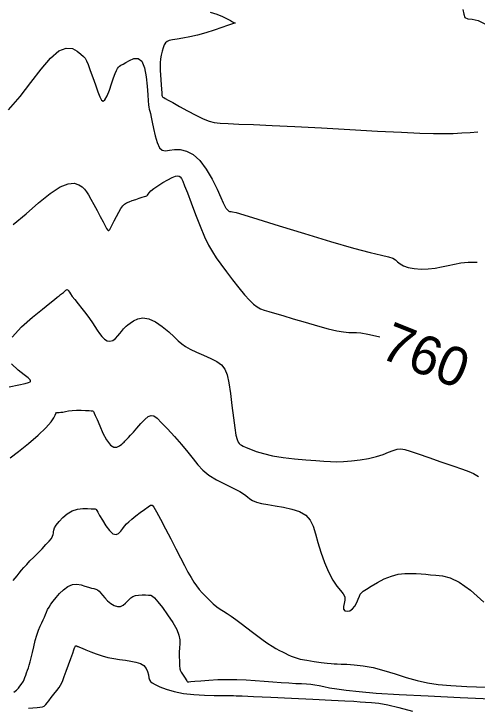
# Model space of a CAD drawing. Extents: x 2566142 to 2571431, y 418755 to 421584.
# Drawn here: x 2570563.2 to 2570801.1, y 420602.2 to 420960.2 of the extents above; entities that cross this region are included whole.
import ezdxf

# ---------------------------------------------------------------- set-up
doc = ezdxf.new("R2010")
doc.units = 0
for name, color, linetype in [('Contour_ADS_Label_Major', 7, 'Continuous'), ('Contour_ADS_Major', 7, 'Continuous'), ('Contour_ADS_Minor', 7, 'Continuous')]:
    doc.layers.add(name, color=color, linetype=linetype)

msp = doc.modelspace()

# ---------------------------------------------------------------- linework, layer by layer
at = {"layer": 'Contour_ADS_Major'}
for points in [[(2570562.7, 420851.9), (2570569.36, 420857.45), (2570575.83, 420862.95), (2570581.81, 420867.74), (2570586.95, 420871.2), (2570591.03, 420872.87), (2570594.14, 420873.09), (2570596.46, 420872.36), (2570598.16, 420871.2), (2570599.42, 420870.01), (2570600.45, 420868.71), (2570601.46, 420867.09), (2570602.64, 420864.95), (2570604.14, 420862.17), (2570605.83, 420859.04), (2570607.5, 420855.93), (2570608.93, 420853.22), (2570609.99, 420851.21), (2570610.71, 420849.88), (2570611.22, 420849.11), (2570611.59, 420848.8), (2570611.94, 420848.87), (2570612.35, 420849.36), (2570612.88, 420850.31), (2570613.62, 420851.79), (2570614.61, 420853.78), (2570615.76, 420856.06), (2570616.96, 420858.29), (2570618.07, 420860.19), (2570619.03, 420861.53), (2570619.95, 420862.41), (2570620.98, 420863.02), (2570622.27, 420863.56), (2570623.93, 420864.17), (2570625.77, 420864.81), (2570627.57, 420865.42), (2570629.11, 420865.91), (2570630.21, 420866.24), (2570630.94, 420866.47), (2570631.41, 420866.69), (2570631.75, 420867.01), (2570632.09, 420867.49), (2570632.61, 420868.19), (2570633.52, 420869.14), (2570634.99, 420870.35), (2570637.13, 420871.83), (2570639.68, 420873.41), (2570642.26, 420874.88), (2570644.51, 420876.04), (2570646.16, 420876.73), (2570647.29, 420876.97), (2570648.05, 420876.82), (2570648.63, 420876.35), (2570649.19, 420875.56), (2570649.88, 420874.17), (2570650.85, 420871.82), (2570652.25, 420868.18), (2570654.17, 420863.06), (2570656.44, 420857.06), (2570658.84, 420850.94), (2570661.13, 420845.47), (2570663.16, 420841.2), (2570665.08, 420837.8), (2570667.12, 420834.72), (2570669.5, 420831.44), (2570672.36, 420827.56), (2570675.52, 420823.35), (2570678.7, 420819.23), (2570681.63, 420815.64), (2570684.11, 420812.89), (2570686.2, 420810.9), (2570688.07, 420809.51), (2570689.86, 420808.53), (2570691.74, 420807.77), (2570694.04, 420807.07), (2570697.09, 420806.22), (2570701.24, 420805.05), (2570706.65, 420803.44), (2570712.81, 420801.59), (2570719.04, 420799.76), (2570724.65, 420798.24), (2570729.11, 420797.21), (2570732.52, 420796.63), (2570735.13, 420796.37), (2570737.21, 420796.3), (2570739.08, 420796.29), (2570741.42, 420796.1), (2570744.97, 420795.51), (2570750.48, 420794.27), (2570751.11, 420794.11)], [(2570570.7, 420603.19), (2570575.15, 420603.52), (2570577.76, 420603.88), (2570578.61, 420604.2), (2570579.07, 420604.55), (2570579.54, 420605.04), (2570580.14, 420605.8), (2570581.03, 420606.95), (2570582.27, 420608.55), (2570583.71, 420610.4), (2570585.14, 420612.25), (2570586.33, 420613.84), (2570587.16, 420615.03), (2570587.74, 420616.09), (2570588.28, 420617.4), (2570589, 420619.35), (2570590.01, 420622.16), (2570591.21, 420625.46), (2570592.4, 420628.72), (2570593.37, 420631.43), (2570594.01, 420633.19), (2570594.34, 420634.14), (2570594.5, 420634.57), (2570594.56, 420634.74), (2570594.64, 420634.88), (2570594.73, 420635.02), (2570594.84, 420635.14), (2570594.97, 420635.21), (2570595.11, 420635.21), (2570595.27, 420635.16), (2570595.43, 420635.09), (2570595.59, 420635.01), (2570595.78, 420634.93), (2570596.15, 420634.79), (2570596.89, 420634.5), (2570598.16, 420633.96), (2570600.1, 420633.13), (2570602.58, 420632.12), (2570605.42, 420631.05), (2570608.44, 420630.07), (2570611.47, 420629.28), (2570614.49, 420628.67), (2570617.46, 420628.18), (2570620.39, 420627.76), (2570623.21, 420627.35), (2570625.83, 420626.83), (2570628.1, 420626.11), (2570629.88, 420625.05), (2570631.08, 420623.6), (2570631.81, 420621.92), (2570632.23, 420620.24), (2570632.49, 420618.79), (2570632.76, 420617.71), (2570633.25, 420616.9), (2570634.18, 420616.15), (2570635.77, 420615.29), (2570638.19, 420614.18), (2570641.44, 420612.94), (2570645.47, 420611.74), (2570650.21, 420610.77), (2570655.55, 420610.14), (2570661, 420609.82), (2570666, 420609.69), (2570669.99, 420609.68), (2570672.58, 420609.68), (2570673.99, 420609.69), (2570674.62, 420609.7), (2570674.85, 420609.7), (2570675.02, 420609.7), (2570675.19, 420609.69), (2570675.38, 420609.68), (2570675.6, 420609.66), (2570676.01, 420609.63), (2570677.32, 420609.57), (2570680.43, 420609.43), (2570686.19, 420609.17), (2570695.07, 420608.78), (2570705.82, 420608.31), (2570716.78, 420607.8), (2570726.3, 420607.34), (2570733.12, 420606.96), (2570737.72, 420606.66), (2570740.97, 420606.42), (2570743.75, 420606.22), (2570746.83, 420606.01), (2570750.56, 420605.63), (2570755.19, 420604.87), (2570760.95, 420603.55), (2570767.91, 420601.57)]]:
    msp.add_lwpolyline(points, dxfattribs=at)
at = {"layer": 'Contour_ADS_Minor'}
for points in [[(2570663.9, 420961.1), (2570667.37, 420960.04), (2570670.29, 420958.86), (2570672.63, 420957.72), (2570674.36, 420956.79), (2570675.51, 420956.18), (2570676.19, 420955.84), (2570676.53, 420955.68), (2570676.69, 420955.61), (2570676.78, 420955.57), (2570676.83, 420955.53), (2570676.84, 420955.5), (2570676.81, 420955.47), (2570676.75, 420955.44), (2570676.67, 420955.41), (2570676.57, 420955.39), (2570676.47, 420955.37), (2570676.33, 420955.34), (2570675.9, 420955.21), (2570674.86, 420954.87), (2570672.92, 420954.2), (2570669.89, 420953.13), (2570666.03, 420951.83), (2570661.75, 420950.47), (2570657.45, 420949.26), (2570653.45, 420948.35), (2570649.92, 420947.69), (2570646.93, 420947.21), (2570644.58, 420946.83), (2570642.91, 420946.45), (2570641.79, 420945.96), (2570641.02, 420945.25), (2570640.41, 420944.21), (2570639.82, 420942.74), (2570639.27, 420940.96), (2570638.79, 420939.01), (2570638.45, 420937.01), (2570638.29, 420935.07), (2570638.26, 420933.13), (2570638.34, 420931.08), (2570638.47, 420928.83), (2570638.62, 420926.33), (2570638.77, 420923.79), (2570638.92, 420921.47), (2570639.05, 420919.64), (2570639.17, 420918.47), (2570639.3, 420917.84), (2570639.47, 420917.55), (2570639.71, 420917.39), (2570640.1, 420917.16), (2570640.87, 420916.71), (2570642.31, 420915.88), (2570644.7, 420914.54), (2570648.19, 420912.62), (2570652.35, 420910.37), (2570656.63, 420908.15), (2570660.44, 420906.29), (2570663.44, 420905.05), (2570666.1, 420904.34), (2570669.1, 420903.97), (2570673.13, 420903.75), (2570678.77, 420903.53), (2570686.26, 420903.23), (2570695.76, 420902.82), (2570707.42, 420902.25)], [(2570793.83, 420962.37), (2570794.25, 420960.06), (2570794.82, 420958.41), (2570796.3, 420957.73), (2570798.65, 420957.46), (2570801.63, 420956.84), (2570804.99, 420955.09), (2570808.5, 420951.68), (2570811.96, 420947.09), (2570815.19, 420942.08), (2570818.01, 420937.38), (2570820.33, 420933.56), (2570822.49, 420930.46), (2570824.92, 420927.76), (2570828.03, 420925.15), (2570832.08, 420922.38), (2570836.61, 420919.63), (2570841, 420917.15), (2570844.61, 420915.2), (2570846.97, 420913.96), (2570848.29, 420913.29), (2570848.91, 420913), (2570849.2, 420912.87)], [(2570560.43, 420910.9), (2570566.27, 420917.78), (2570571.86, 420924.96), (2570577.11, 420931.74), (2570581.94, 420937.4), (2570586.27, 420941.19), (2570590.02, 420942.65), (2570593.16, 420942.31), (2570595.67, 420940.97), (2570597.55, 420939.44), (2570598.82, 420938.31), (2570599.69, 420937.34), (2570600.4, 420936.08), (2570601.22, 420934.1)], [(2570601.22, 420934.1), (2570602.32, 420931.11), (2570603.63, 420927.45), (2570604.98, 420923.63), (2570606.22, 420920.17), (2570607.25, 420917.49), (2570608.13, 420915.82), (2570608.98, 420915.28), (2570609.91, 420916.04), (2570611, 420918.11), (2570612.18, 420921.05), (2570613.34, 420924.29), (2570614.35, 420927.27), (2570615.15, 420929.53), (2570615.77, 420931.12), (2570616.3, 420932.18), (2570616.81, 420932.87), (2570617.39, 420933.35), (2570618.15, 420933.77), (2570619.2, 420934.31), (2570620.67, 420935.14), (2570622.6, 420936.28), (2570624.78, 420937.22), (2570626.94, 420937.3), (2570628.79, 420935.86), (2570630.15, 420932.51), (2570631.04, 420927.9), (2570631.6, 420922.94), (2570631.93, 420918.56), (2570632.14, 420915.45), (2570632.3, 420913.43), (2570632.44, 420912.14), (2570632.63, 420911.18), (2570632.89, 420910.19), (2570633.25, 420908.92), (2570633.7, 420907.13), (2570634.25, 420904.59), (2570634.91, 420901.21), (2570635.71, 420897.47), (2570636.69, 420893.99), (2570637.87, 420891.39), (2570639.3, 420890.11), (2570641.04, 420889.85), (2570643.13, 420890.14), (2570645.63, 420890.48), (2570648.56, 420890.43), (2570651.81, 420889.67), (2570655.23, 420887.91), (2570658.66, 420884.87), (2570661.96, 420880.42), (2570664.97, 420875.23), (2570667.53, 420870.09), (2570669.48, 420865.84), (2570670.71, 420863.09), (2570671.38, 420861.61), (2570671.68, 420860.96), (2570671.83, 420860.7), (2570671.99, 420860.45), (2570672.19, 420860.18), (2570672.44, 420859.87), (2570672.72, 420859.55), (2570673.02, 420859.24), (2570673.34, 420858.96), (2570673.63, 420858.73), (2570673.88, 420858.58), (2570674.07, 420858.53), (2570674.26, 420858.55), (2570674.49, 420858.58), (2570674.83, 420858.59), (2570675.5, 420858.48), (2570677.33, 420857.99), (2570681.33, 420856.81), (2570688.5, 420854.6), (2570699.36, 420851.24), (2570712.45, 420847.2), (2570725.84, 420843.16), (2570737.59, 420839.76), (2570746.2, 420837.5), (2570751.95, 420836.15), (2570755.56, 420835.31), (2570757.74, 420834.6), (2570759.17, 420833.71), (2570760.29, 420832.66), (2570761.5, 420831.59), (2570763.22, 420830.6), (2570765.72, 420829.81), (2570768.85, 420829.26), (2570772.36, 420828.99), (2570775.97, 420829.04), (2570779.48, 420829.41), (2570782.87, 420830.03), (2570786.19, 420830.78), (2570789.46, 420831.55), (2570792.8, 420832.22), (2570796.56, 420832.59), (2570801.16, 420832.44)], [(2570707.42, 420902.25), (2570721.11, 420901.53), (2570735.73, 420900.72), (2570749.9, 420899.94), (2570762.22, 420899.29), (2570771.7, 420898.85), (2570778.76, 420898.63), (2570784.19, 420898.6), (2570788.79, 420898.72), (2570793.2, 420898.96), (2570797.46, 420899.25), (2570801.43, 420899.5)], [(2570562.17, 420793.96), (2570567, 420799.29), (2570572.64, 420804.27), (2570577.83, 420808.42), (2570581.56, 420811.39), (2570583.97, 420813.32), (2570585.43, 420814.52), (2570586.35, 420815.26), (2570587.05, 420815.81), (2570587.63, 420816.25), (2570588.13, 420816.63), (2570588.6, 420816.98), (2570589.05, 420817.36), (2570589.48, 420817.72), (2570589.87, 420818.04), (2570590.21, 420818.27), (2570590.48, 420818.37), (2570590.72, 420818.32), (2570590.97, 420818.1), (2570591.26, 420817.7), (2570591.66, 420817.09), (2570592.24, 420816.19), (2570593.11, 420814.93), (2570594.37, 420813.24), (2570596.07, 420811.09), (2570598.04, 420808.62), (2570600.07, 420806.05), (2570601.93, 420803.58), (2570603.49, 420801.36), (2570604.79, 420799.38), (2570605.96, 420797.57), (2570607.12, 420795.89), (2570608.36, 420794.31), (2570609.7, 420792.97), (2570611.08, 420792.08), (2570612.5, 420791.81), (2570613.91, 420792.28), (2570615.25, 420793.28), (2570616.48, 420794.55), (2570617.52, 420795.8), (2570618.33, 420796.8), (2570618.95, 420797.57), (2570619.45, 420798.17), (2570619.89, 420798.67), (2570620.33, 420799.14), (2570620.89, 420799.66), (2570621.71, 420800.31), (2570622.91, 420801.19), (2570624.59, 420802.29), (2570626.77, 420803.3), (2570629.39, 420803.8), (2570632.45, 420803.4), (2570635.85, 420801.85), (2570639.35, 420799.47), (2570642.65, 420796.75), (2570645.46, 420794.17), (2570647.6, 420792.11), (2570649.39, 420790.47), (2570651.26, 420789.08), (2570653.66, 420787.72), (2570656.86, 420786.25), (2570660.55, 420784.68), (2570664.23, 420783.04), (2570667.45, 420781.37), (2570669.82, 420779.65), (2570671.48, 420777.55), (2570672.64, 420774.65), (2570673.54, 420770.53), (2570674.36, 420765.01), (2570675.15, 420758.73), (2570675.89, 420752.53), (2570676.57, 420747.27), (2570677.2, 420743.59), (2570677.79, 420741.3), (2570678.33, 420740.01), (2570678.83, 420739.3), (2570679.33, 420738.82), (2570679.98, 420738.41), (2570680.97, 420737.93), (2570682.47, 420737.27), (2570684.66, 420736.33), (2570687.6, 420735.22)], [(2570560.77, 420768.42), (2570565.72, 420769.35), (2570568.95, 420770.05), (2570570.68, 420770.55), (2570571.42, 420770.91), (2570571.64, 420771.2), (2570571.7, 420771.51), (2570571.41, 420772.03), (2570570.42, 420772.99), (2570568.4, 420774.58), (2570565.26, 420776.99), (2570561.93, 420780.19)], [(2570561.25, 420731.81), (2570565.54, 420735.18), (2570570.57, 420739.28), (2570575.52, 420743.54), (2570579.61, 420747.38), (2570582.23, 420750.35), (2570583.65, 420752.47), (2570584.29, 420753.88), (2570584.63, 420754.73), (2570585.04, 420755.14), (2570585.6, 420755.27), (2570586.32, 420755.27), (2570587.21, 420755.29), (2570588.27, 420755.44), (2570589.56, 420755.7), (2570591.13, 420755.97), (2570593.04, 420756.2), (2570595.3, 420756.32), (2570597.68, 420756.35), (2570599.91, 420756.3), (2570601.72, 420756.22), (2570602.91, 420756.11), (2570603.57, 420755.98), (2570603.89, 420755.83), (2570604.04, 420755.66), (2570604.18, 420755.42), (2570604.45, 420754.85), (2570604.96, 420753.65), (2570605.86, 420751.52), (2570607.2, 420748.32), (2570608.89, 420744.6), (2570610.77, 420741.07), (2570612.68, 420738.47), (2570614.48, 420737.31), (2570616.09, 420737.31), (2570617.47, 420737.98), (2570618.54, 420738.84), (2570619.28, 420739.52), (2570619.79, 420740.01), (2570620.2, 420740.43), (2570620.63, 420740.89), (2570621.21, 420741.48), (2570622.01, 420742.32), (2570623.09, 420743.5), (2570624.52, 420745.12), (2570626.31, 420747.21), (2570628.31, 420749.47), (2570630.32, 420751.54), (2570632.14, 420753.07), (2570633.65, 420753.73), (2570635.09, 420753.45), (2570636.77, 420752.2), (2570639.03, 420749.95), (2570642.06, 420746.73), (2570645.59, 420742.88), (2570649.21, 420738.78), (2570652.51, 420734.82), (2570655.24, 420731.32), (2570657.67, 420728.25), (2570660.24, 420725.5), (2570663.36, 420722.97), (2570667.29, 420720.58), (2570671.63, 420718.34), (2570675.81, 420716.31), (2570679.26, 420714.53)], [(2570687.6, 420735.22), (2570691.37, 420734.06), (2570696.01, 420732.99), (2570701.48, 420732.12), (2570707.36, 420731.44), (2570713.13, 420730.9), (2570718.27, 420730.48), (2570722.41, 420730.14), (2570725.86, 420729.92), (2570729.08, 420729.84), (2570732.54, 420729.95), (2570736.58, 420730.27), (2570740.97, 420730.81), (2570745.36, 420731.55), (2570749.4, 420732.5), (2570752.82, 420733.61), (2570755.65, 420734.73), (2570758.02, 420735.7), (2570760.03, 420736.34), (2570761.88, 420736.5), (2570763.98, 420736.15), (2570766.79, 420735.28), (2570770.81, 420733.88), (2570776.27, 420732.01), (2570782.5, 420729.9), (2570788.57, 420727.84), (2570793.57, 420726.14), (2570796.92, 420724.94), (2570799.33, 420723.82), (2570801.85, 420722.22)], [(2570679.26, 420714.53), (2570681.59, 420713.04), (2570683.11, 420711.8), (2570684.33, 420710.77), (2570685.73, 420709.9), (2570687.72, 420709.15), (2570690.35, 420708.48), (2570693.58, 420707.83), (2570697.35, 420707.18), (2570701.56, 420706.45), (2570705.87, 420705.51), (2570709.86, 420704.2), (2570713.12, 420702.35), (2570715.36, 420699.84), (2570716.86, 420696.66), (2570718.02, 420692.82), (2570719.22, 420688.34), (2570720.77, 420683.3), (2570722.66, 420678.1), (2570724.75, 420673.2), (2570726.91, 420669.04), (2570729.03, 420665.95), (2570730.91, 420663.72), (2570732.35, 420661.99), (2570733.15, 420660.4), (2570733.22, 420658.69), (2570732.85, 420656.95), (2570732.46, 420655.35), (2570732.44, 420654.07), (2570733.1, 420653.26), (2570734.27, 420652.99), (2570735.69, 420653.28), (2570737.11, 420654.16), (2570738.31, 420655.62), (2570739.28, 420657.41), (2570740.03, 420659.21), (2570740.6, 420660.73), (2570741.07, 420661.76), (2570741.65, 420662.49), (2570742.63, 420663.24), (2570744.27, 420664.3), (2570746.75, 420665.87), (2570749.89, 420667.74), (2570753.41, 420669.58), (2570757.05, 420671.08), (2570760.57, 420671.99), (2570763.89, 420672.4), (2570766.97, 420672.47), (2570769.77, 420672.35), (2570772.3, 420672.18), (2570774.7, 420672), (2570777.2, 420671.78), (2570779.98, 420671.54), (2570783.24, 420671.16), (2570787.18, 420670.15), (2570791.96, 420667.9), (2570797.78, 420663.81), (2570804.64, 420657.58)], [(2570562.77, 420668.76), (2570563.82, 420669.93), (2570564.84, 420671.23), (2570565.9, 420672.6), (2570567.04, 420674.04), (2570568.32, 420675.53), (2570569.76, 420677.1), (2570571.4, 420678.83), (2570573.29, 420680.76), (2570575.41, 420682.9), (2570577.59, 420685.13), (2570579.61, 420687.24), (2570581.26, 420689.07), (2570582.37, 420690.48), (2570583.02, 420691.54), (2570583.33, 420692.37), (2570583.45, 420693.09), (2570583.51, 420693.84), (2570583.66, 420694.71), (2570584.07, 420695.82), (2570584.92, 420697.3), (2570586.32, 420699.17), (2570588.21, 420701.23), (2570590.5, 420703.15), (2570593.07, 420704.65), (2570595.82, 420705.51), (2570598.52, 420705.84), (2570600.95, 420705.84), (2570602.88, 420705.72), (2570604.14, 420705.63), (2570604.84, 420705.57), (2570605.18, 420705.52), (2570605.32, 420705.44), (2570605.45, 420705.27), (2570605.7, 420704.82), (2570606.22, 420703.87), (2570607.15, 420702.21), (2570608.57, 420699.75), (2570610.32, 420696.96), (2570612.21, 420694.43), (2570614.02, 420692.76), (2570615.59, 420692.37), (2570616.92, 420693.01), (2570618.07, 420694.23), (2570619.06, 420695.61), (2570619.98, 420696.81), (2570620.95, 420697.89), (2570622.15, 420699.02), (2570623.74, 420700.34), (2570625.79, 420701.97), (2570628.08, 420703.73), (2570630.29, 420705.39), (2570632.1, 420706.74), (2570633.3, 420707.54), (2570634.18, 420707.55), (2570635.09, 420706.49), (2570636.43, 420704.11), (2570638.46, 420700.29), (2570640.99, 420695.45), (2570643.74, 420690.17), (2570646.4, 420685), (2570648.75, 420680.41), (2570650.78, 420676.46), (2570652.55, 420673.1), (2570654.12, 420670.29), (2570655.56, 420667.97), (2570656.94, 420666), (2570658.37, 420664.2), (2570659.93, 420662.43), (2570661.68, 420660.55), (2570663.55, 420658.66), (2570665.46, 420656.87), (2570667.32, 420655.31), (2570669.06, 420654.05), (2570670.79, 420652.95), (2570672.64, 420651.81), (2570674.75, 420650.44), (2570677.22, 420648.69), (2570679.96, 420646.64), (2570682.83, 420644.44), (2570685.72, 420642.22)], [(2570563.08, 420611.43), (2570564.46, 420612.45), (2570565.49, 420613.46), (2570566.25, 420614.41), (2570566.83, 420615.23), (2570567.29, 420615.9), (2570567.67, 420616.48), (2570568.03, 420617.11), (2570568.39, 420617.89), (2570568.79, 420618.9), (2570569.22, 420620.09), (2570569.67, 420621.38), (2570570.12, 420622.68), (2570570.56, 420623.95), (2570571.01, 420625.32), (2570571.49, 420626.98), (2570572.02, 420629.09), (2570572.62, 420631.76), (2570573.3, 420634.77), (2570574.04, 420637.86), (2570574.86, 420640.74), (2570575.74, 420643.19), (2570576.62, 420645.24), (2570577.46, 420646.98), (2570578.2, 420648.51), (2570578.81, 420649.91), (2570579.33, 420651.23), (2570579.85, 420652.52), (2570580.45, 420653.82), (2570581.18, 420655.17), (2570582.12, 420656.62), (2570583.31, 420658.23), (2570584.79, 420660.05), (2570586.6, 420662.06), (2570588.66, 420664.04), (2570590.88, 420665.69), (2570593.17, 420666.73), (2570595.45, 420666.97), (2570597.63, 420666.61), (2570599.65, 420665.95), (2570601.43, 420665.3), (2570602.93, 420664.89), (2570604.17, 420664.64), (2570605.21, 420664.39), (2570606.11, 420663.99), (2570606.91, 420663.31), (2570607.73, 420662.37), (2570608.66, 420661.2), (2570609.82, 420659.85), (2570611.26, 420658.39), (2570612.91, 420657), (2570614.64, 420655.92), (2570616.32, 420655.35), (2570617.87, 420655.47), (2570619.25, 420656.11), (2570620.46, 420657.06), (2570621.5, 420658.11), (2570622.39, 420659.08), (2570623.25, 420659.89), (2570624.25, 420660.55), (2570625.52, 420661.01), (2570627.16, 420661.27), (2570628.99, 420661.36), (2570630.78, 420661.36), (2570632.3, 420661.31), (2570633.41, 420661.21), (2570634.34, 420660.82), (2570635.45, 420659.81), (2570637.07, 420657.89), (2570639.4, 420654.88), (2570642.11, 420651.15), (2570644.73, 420647.22), (2570646.79, 420643.6), (2570647.95, 420640.67), (2570648.38, 420638.29), (2570648.36, 420636.2), (2570648.18, 420634.13), (2570648.08, 420631.89), (2570648.08, 420629.61), (2570648.13, 420627.51), (2570648.22, 420625.8), (2570648.29, 420624.63), (2570648.36, 420623.91), (2570648.41, 420623.5), (2570648.45, 420623.25), (2570648.5, 420623.03)], [(2570685.72, 420642.22), (2570688.5, 420640.1), (2570691.13, 420638.15), (2570693.56, 420636.42), (2570695.78, 420634.96), (2570697.75, 420633.8), (2570699.5, 420632.87), (2570701.09, 420632.09), (2570702.55, 420631.36), (2570703.97, 420630.62), (2570705.56, 420629.87), (2570707.55, 420629.13), (2570710.18, 420628.42), (2570713.58, 420627.76), (2570717.35, 420627.18), (2570721.02, 420626.7), (2570724.07, 420626.34), (2570726.19, 420626.11), (2570727.73, 420625.97), (2570729.24, 420625.9), (2570731.25, 420625.85), (2570734.18, 420625.76), (2570737.99, 420625.51), (2570742.54, 420624.97), (2570747.66, 420624.01), (2570753.2, 420622.55), (2570758.95, 420620.79), (2570764.72, 420618.97), (2570770.28, 420617.37), (2570775.59, 420616.18), (2570781.16, 420615.34), (2570787.66, 420614.76), (2570795.76, 420614.32), (2570805.81, 420613.95)], [(2570648.5, 420623.03), (2570648.59, 420622.73), (2570648.79, 420622.3), (2570649.15, 420621.63), (2570649.7, 420620.7), (2570650.37, 420619.63), (2570651.04, 420618.58), (2570651.6, 420617.72), (2570651.99, 420617.16), (2570652.21, 420616.86), (2570652.34, 420616.74), (2570652.42, 420616.71), (2570652.55, 420616.71), (2570653, 420616.74), (2570654.08, 420616.82), (2570656.09, 420617), (2570659.24, 420617.28), (2570663.31, 420617.58), (2570667.95, 420617.84), (2570672.83, 420617.97), (2570677.68, 420617.9), (2570682.44, 420617.68), (2570687.12, 420617.36), (2570691.71, 420617.01), (2570696.19, 420616.67), (2570700.47, 420616.37), (2570704.42, 420616.11), (2570707.91, 420615.9), (2570710.88, 420615.75), (2570713.41, 420615.61), (2570715.66, 420615.43), (2570717.77, 420615.16), (2570719.92, 420614.77), (2570722.33, 420614.26), (2570725.28, 420613.67), (2570729.02, 420613.03), (2570733.88, 420612.36), (2570740.43, 420611.66), (2570749.29, 420610.94), (2570761.1, 420610.18), (2570776.03, 420609.4), (2570792.43, 420608.62), (2570808.19, 420607.88)]]:
    msp.add_lwpolyline(points, dxfattribs=at)

# ---------------------------------------------------------------- texts
at = {"layer": 'Contour_ADS_Label_Major'}
msp.add_text('760', height=20, rotation=338.2797, dxfattribs=at).set_placement((2570750.32, 420783.66))

doc.saveas('drawing.dxf')
